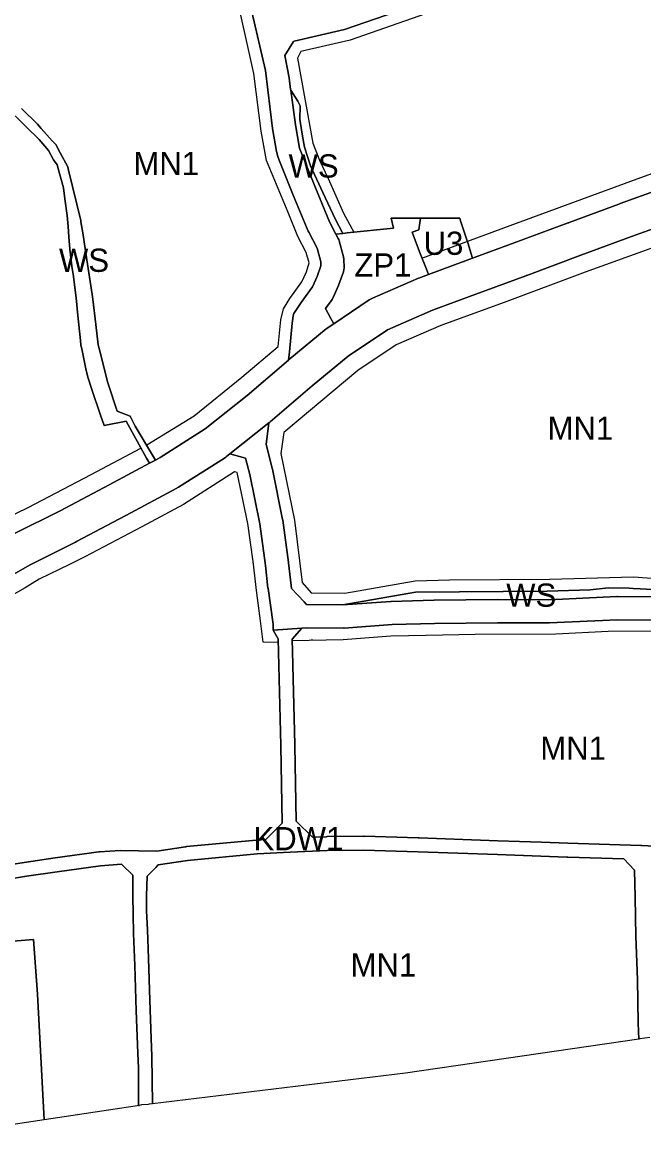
# Model space of a CAD drawing. Extents: x -284239 to -281592, y 34477 to 37267.
# Drawn here: x -283094 to -282826.9, y 34607.5 to 35089.5 of the extents above; entities that cross this region are included whole.
import ezdxf

# ---------------------------------------------------------------- set-up
doc = ezdxf.new("R2010")
doc.units = 0
for name, color, linetype in [('linie_rozgraniczajace', 7, 'Continuous'), ('linie_zabudowy_nieprzekraczalne', 7, 'Continuous'), ('oznaczenia_przeznaczen', 7, 'Continuous')]:
    doc.layers.add(name, color=color, linetype=linetype)

msp = doc.modelspace()

# ---------------------------------------------------------------- linework, layer by layer
at = {"layer": 'linie_rozgraniczajace'}
for points in [[(-282984.261, 35031.801), (-282984.727, 35033.927), (-282986.536, 35043.847), (-282986.543, 35043.898), (-282989.562, 35068.789), (-282995.429, 35094.107), (-282997.964, 35106.782), (-282997.992, 35107.066), (-282998.031, 35107.22), (-282999.546, 35121.106), (-283000.607, 35130.234), (-283002.988, 35136.929), (-283006.698, 35143.047), (-283012.879, 35144.669), (-283014.237, 35143.768), (-283014.294, 35143.738), (-283014.337, 35143.704), (-283037.155, 35129.353), (-283037.6, 35129.123), (-283037.687, 35129.062), (-283050.882, 35122.865), (-283072.146, 35113.651), (-283108.433, 35098.389)], [(-282888.924, 35109.624), (-282955.467, 35086.473), (-282977.23, 35081.468), (-282977.427, 35081.287), (-282981.158, 35075.35), (-282979.397, 35065.606), (-282978.732, 35060.692), (-282978.682, 35060.321), (-282976.677, 35045.517), (-282974.931, 35035.403), (-282974.367, 35034.009), (-282968.305, 35019.008), (-282961.945, 35003.744), (-282959.201, 34998.435), (-282958.219, 34996.535), (-282958.042, 34996.153), (-282957.836, 34995.549), (-282955.951, 34988.604), (-282955.825, 34987.656), (-282955.778, 34987.441), (-282955.679, 34984.068), (-282955.692, 34983.997), (-282955.677, 34983.92), (-282955.968, 34982.239), (-282957.953, 34976.682), (-282958.066, 34976.504), (-282958.113, 34976.289), (-282960.444, 34971.179), (-282960.537, 34971.045), (-282960.913, 34970.364), (-282963.722, 34966.398), (-282961.42, 34962.059), (-282960.194, 34959.875), (-282962.551, 34958.298), (-282963.138, 34957.816), (-282963.415, 34957.649), (-282978.997, 34944.716), (-282979.222, 34944.512), (-282979.282, 34944.474), (-282979.59, 34944.211), (-282979.251, 34947.75), (-282978.03, 34960.157), (-282977.949, 34961.052), (-282977.552, 34963.234), (-282977.253, 34964.253), (-282976.76, 34965.164), (-282974.18, 34968.934), (-282974.151, 34968.968), (-282974.133, 34969), (-282969.346, 34975.759), (-282967.299, 34980.246), (-282965.703, 34984.715), (-282965.757, 34986.555), (-282967.347, 34992.416), (-282970.923, 34999.336), (-282971.096, 34999.707), (-282977.567, 35015.236), (-282983.609, 35030.188), (-282984.261, 35031.801)], [(-282814.671, 35019.595), (-282837.032, 35011.566), (-282837.249, 35011.428), (-282837.567, 35011.371), (-282858.94, 35003.467), (-282859.141, 35003.338), (-282859.425, 35003.287), (-282882.548, 34994.655), (-282900.47, 34988.07), (-282901.252, 34990.443), (-282902.422, 34994.245), (-282905.721, 35004.142), (-282905.941, 35005.352), (-282922.86, 35005.352), (-282935.414, 35005.352), (-282934.534, 35000.953), (-282954.439, 34998.974), (-282955.226, 34998.885), (-282956.293, 34998.764), (-282959.504, 35005.043), (-282964.821, 35016.354), (-282970.138, 35027.76), (-282972.748, 35035.881), (-282973.811, 35041.391), (-282974.778, 35047.868), (-282974.584, 35053.668), (-282975.648, 35055.698), (-282978.682, 35060.321), (-282978.732, 35060.692), (-282979.397, 35065.606), (-282981.158, 35075.35), (-282977.427, 35081.287), (-282977.23, 35081.468), (-282955.467, 35086.473), (-282888.924, 35109.624)], [(-282995.429, 35094.107), (-282989.562, 35068.789), (-282986.543, 35043.898), (-282986.536, 35043.847), (-282984.727, 35033.927), (-282984.261, 35031.801), (-282983.609, 35030.188), (-282977.567, 35015.236), (-282971.096, 34999.707), (-282970.923, 34999.336), (-282967.347, 34992.416), (-282965.757, 34986.555), (-282965.703, 34984.715), (-282967.299, 34980.246), (-282969.346, 34975.759), (-282974.133, 34969), (-282974.151, 34968.968), (-282974.18, 34968.934), (-282976.76, 34965.164), (-282977.253, 34964.253), (-282977.552, 34963.234), (-282977.949, 34961.052), (-282978.03, 34960.157), (-282979.251, 34947.75), (-282979.59, 34944.211), (-282997.369, 34928.976), (-283015.4, 34914.591), (-283034.85, 34902.276), (-283036.848, 34901.207), (-283038.115, 34903.36), (-283045.51, 34915.78), (-283047.764, 34920.051), (-283053.281, 34922.246), (-283057.226, 34934.495), (-283059.242, 34942.266), (-283060.251, 34946.419), (-283061.408, 34950.779), (-283062.475, 34959.558), (-283063.692, 34970.503), (-283063.999, 34972.423), (-283066.274, 34987.41), (-283068.022, 34998.977), (-283068.852, 35003.722), (-283068.95, 35004.294), (-283074.187, 35025.877), (-283074.429, 35027.45), (-283077.75, 35033.442), (-283079.619, 35036.971), (-283081.161, 35038.632), (-283085.966, 35043.912), (-283087.568, 35045.691), (-283094.449, 35052.454)], [(-283101.538, 35053.67), (-283092.254, 35044.386), (-283086.886, 35039.136), (-283082.793, 35034.45), (-283080.598, 35030.416), (-283079.115, 35028.221), (-283078.551, 35026.116), (-283076.653, 35019.353), (-283076.356, 35018.285), (-283075.763, 35013.54), (-283074.725, 35006.392), (-283074.31, 35001.705), (-283074.073, 34997.256), (-283073.687, 34991.947), (-283072.738, 34984.591), (-283072.597, 34983.582), (-283072.256, 34981.13), (-283070.968, 34971.055), (-283070.128, 34963.414), (-283069.09, 34952.707), (-283068.852, 34950.749), (-283068.318, 34948.377), (-283066.568, 34939.686), (-283065.738, 34936.423), (-283064.314, 34932.034), (-283060.429, 34920.555), (-283058.916, 34916.017), (-283049.425, 34917.975), (-283040.607, 34902.026), (-283039.34, 34899.873), (-283056.665, 34890.604), (-283077.823, 34879.372), (-283097.47, 34869.563)], [(-283094.449, 35052.454), (-283087.568, 35045.691), (-283085.966, 35043.912), (-283081.161, 35038.632), (-283079.619, 35036.971), (-283077.75, 35033.442), (-283074.429, 35027.45), (-283074.187, 35025.877), (-283068.95, 35004.294), (-283068.852, 35003.722), (-283068.022, 34998.977), (-283066.274, 34987.41), (-283063.999, 34972.423), (-283063.692, 34970.503), (-283062.475, 34959.558), (-283061.408, 34950.779), (-283060.251, 34946.419), (-283059.242, 34942.266), (-283057.226, 34934.495), (-283053.281, 34922.246), (-283047.764, 34920.051), (-283045.51, 34915.78), (-283038.115, 34903.36), (-283036.848, 34901.207), (-283039.34, 34899.873), (-283040.607, 34902.026), (-283049.425, 34917.975), (-283058.916, 34916.017), (-283060.429, 34920.555), (-283064.314, 34932.034), (-283065.738, 34936.423), (-283066.568, 34939.686), (-283068.318, 34948.377), (-283068.852, 34950.749), (-283069.09, 34952.707), (-283070.128, 34963.414), (-283070.968, 34971.055), (-283072.256, 34981.13), (-283072.597, 34983.582), (-283072.738, 34984.591), (-283073.687, 34991.947), (-283074.073, 34997.256), (-283074.31, 35001.705), (-283074.725, 35006.392), (-283075.763, 35013.54), (-283076.356, 35018.285), (-283076.653, 35019.353), (-283078.551, 35026.116), (-283079.115, 35028.221), (-283080.598, 35030.416), (-283082.793, 35034.45), (-283086.886, 35039.136), (-283092.254, 35044.386), (-283101.538, 35053.67)], [(-282903.935, 34986.797), (-282900.47, 34988.07), (-282882.548, 34994.655), (-282859.425, 35003.287), (-282859.141, 35003.338), (-282858.94, 35003.467), (-282837.567, 35011.371), (-282837.249, 35011.428), (-282837.032, 35011.566), (-282814.671, 35019.595)], [(-282809.83, 35005.391), (-282832.188, 34997.363), (-282853.979, 34989.304), (-282877.109, 34980.67), (-282877.403, 34980.617), (-282877.61, 34980.485), (-282899.009, 34972.622), (-282917.668, 34965.729), (-282937.057, 34957.308), (-282953.985, 34945.976), (-282969.414, 34933.171), (-282987.556, 34917.625), (-282987.643, 34917.572), (-282987.964, 34917.285), (-282988.027, 34917.234), (-283004.812, 34903.844), (-283006.225, 34902.716), (-283006.598, 34902.497), (-283007.144, 34902.059), (-283026.964, 34889.51), (-283027.497, 34889.233), (-283027.692, 34889.089)], [(-282803.33, 34844.5), (-282828.459, 34845.767), (-282831.371, 34845.965), (-282831.573, 34845.958), (-282833.09, 34846.07), (-282842.04, 34846.18), (-282849.95, 34845.359), (-282868.422, 34844.757), (-282925.004, 34844.354), (-282956.239, 34838.916), (-282971.909, 34839.04), (-282972.937, 34840.153), (-282978.282, 34845.943), (-282978.331, 34845.983), (-282978.506, 34847.232), (-282979.567, 34856.984), (-282979.573, 34857.086), (-282982.087, 34875.343), (-282982.121, 34875.469), (-282982.14, 34875.653), (-282986.505, 34897.216), (-282986.614, 34897.573), (-282986.639, 34897.732), (-282989.227, 34907.941), (-282988.027, 34917.234), (-282987.964, 34917.285), (-282987.643, 34917.572), (-282987.556, 34917.625), (-282969.414, 34933.171), (-282953.985, 34945.976), (-282937.057, 34957.308), (-282917.668, 34965.729), (-282899.009, 34972.622), (-282877.61, 34980.485), (-282877.403, 34980.617), (-282877.109, 34980.67), (-282853.979, 34989.304), (-282832.188, 34997.363), (-282809.83, 35005.391)], [(-283097.47, 34869.563), (-283077.823, 34879.372), (-283056.665, 34890.604), (-283039.34, 34899.873), (-283036.848, 34901.207), (-283034.85, 34902.276), (-283015.4, 34914.591), (-282997.369, 34928.976), (-282979.59, 34944.211), (-282979.282, 34944.474), (-282979.222, 34944.512), (-282978.997, 34944.716), (-282963.415, 34957.649), (-282963.138, 34957.816), (-282962.551, 34958.298), (-282960.194, 34959.875), (-282944.943, 34970.085), (-282943.475, 34970.87), (-282943.44, 34970.894), (-282923.689, 34979.473), (-282923.203, 34979.574), (-282922.81, 34979.825), (-282919.422, 34981.077), (-282904.41, 34986.622), (-282904.131, 34986.672), (-282903.935, 34986.797)], [(-283004.812, 34903.844), (-282988.027, 34917.234), (-282989.227, 34907.941), (-282986.639, 34897.732), (-282986.614, 34897.573), (-282986.505, 34897.216), (-282982.14, 34875.653), (-282982.121, 34875.469), (-282982.087, 34875.343), (-282979.573, 34857.086), (-282979.567, 34856.984), (-282978.506, 34847.232), (-282978.331, 34845.983), (-282978.282, 34845.943), (-282972.937, 34840.153), (-282971.909, 34839.04), (-282956.239, 34838.916), (-282935.664, 34840.358), (-282935.574, 34840.343), (-282935.458, 34840.368), (-282917.069, 34840.897), (-282917.03, 34840.89), (-282916.986, 34840.899), (-282889.8, 34841.23), (-282889.755, 34841.221), (-282889.71, 34841.23), (-282867.75, 34841.099), (-282838.448, 34842.481), (-282838.318, 34842.459), (-282838.174, 34842.487), (-282823.206, 34842.374)], [(-283109.417, 34845.453), (-283090.756, 34856.145), (-283071.218, 34865.899), (-283071.156, 34865.944), (-283070.818, 34866.103), (-283049.783, 34877.27), (-283049.73, 34877.309), (-283049.543, 34877.398), (-283027.692, 34889.089), (-283027.497, 34889.233), (-283026.964, 34889.51), (-283007.144, 34902.059), (-283006.598, 34902.497), (-283006.225, 34902.716), (-283004.812, 34903.844), (-282998.149, 34902.078), (-282996.254, 34894.971), (-282991.972, 34873.823), (-282989.49, 34855.795), (-282988.44, 34846.078), (-282988.428, 34846.031), (-282988.42, 34845.92), (-282986.275, 34830.649), (-282986.198, 34827.995), (-282984.083, 34824.23), (-282983.755, 34812.865), (-282982.896, 34778.419), (-282982.278, 34744.959), (-282989.315, 34737.922), (-282993.258, 34737.701), (-282993.296, 34737.692), (-282993.587, 34737.678), (-283023.488, 34734.852), (-283023.583, 34734.829), (-283023.878, 34734.807), (-283036.299, 34732.917), (-283052.013, 34733.25), (-283060.941, 34732.578), (-283060.979, 34732.569), (-283061.115, 34732.56), (-283079.954, 34730.032), (-283079.993, 34730.027), (-283093.246, 34728.035), (-283110.839, 34725.25)], [(-282821.234, 34832.359), (-282838.113, 34832.486), (-282867.411, 34831.103), (-282867.537, 34831.125), (-282867.677, 34831.098), (-282877.381, 34831.156), (-282883.785, 34831.194), (-282889.724, 34831.23), (-282916.823, 34830.9), (-282935.067, 34830.375), (-282955.734, 34828.927), (-282955.913, 34828.956), (-282956.123, 34828.915), (-282971.722, 34829.038), (-282973.902, 34828.881), (-282986.198, 34827.995), (-282986.275, 34830.649), (-282988.42, 34845.92), (-282988.428, 34846.031), (-282988.44, 34846.078), (-282989.49, 34855.795), (-282991.972, 34873.823), (-282996.254, 34894.971), (-282998.149, 34902.078), (-283004.812, 34903.844)], [(-283027.692, 34889.089), (-283049.543, 34877.398), (-283049.73, 34877.309), (-283049.783, 34877.27), (-283070.818, 34866.103), (-283071.156, 34865.944), (-283071.218, 34865.899), (-283090.756, 34856.145), (-283109.417, 34845.453)], [(-282823.206, 34842.374), (-282838.174, 34842.487), (-282838.318, 34842.459), (-282838.448, 34842.481), (-282867.75, 34841.099), (-282889.71, 34841.23), (-282889.755, 34841.221), (-282889.8, 34841.23), (-282916.986, 34840.899), (-282917.03, 34840.89), (-282917.069, 34840.897), (-282935.458, 34840.368), (-282935.574, 34840.343), (-282935.664, 34840.358), (-282956.239, 34838.916), (-282925.004, 34844.354), (-282868.422, 34844.757), (-282849.95, 34845.359), (-282842.04, 34846.18), (-282833.09, 34846.07), (-282831.573, 34845.958), (-282831.371, 34845.965), (-282828.459, 34845.767), (-282803.33, 34844.5)], [(-282803.55, 34733.997), (-282827.697, 34735.363), (-282827.913, 34735.327), (-282828.185, 34735.385), (-282859.477, 34736.305), (-282870.907, 34736.732), (-282880.271, 34737.082), (-282889.562, 34737.429), (-282923.413, 34738.678), (-282923.608, 34738.643), (-282923.837, 34738.692), (-282946.991, 34739.343), (-282947.254, 34739.294), (-282947.528, 34739.347), (-282962.943, 34739.153), (-282963.208, 34739.099), (-282963.437, 34739.14), (-282969.348, 34738.895), (-282976.331, 34745.752), (-282976.894, 34778.354), (-282976.939, 34778.572), (-282976.903, 34778.769), (-282977.753, 34812.837), (-282977.799, 34813.055), (-282977.764, 34813.246), (-282978.051, 34824.157), (-282973.902, 34828.881), (-282971.722, 34829.038), (-282956.123, 34828.915), (-282955.913, 34828.956), (-282955.734, 34828.927), (-282935.067, 34830.375), (-282916.823, 34830.9), (-282889.724, 34831.23), (-282883.785, 34831.194), (-282877.381, 34831.156), (-282867.677, 34831.098), (-282867.537, 34831.125), (-282867.411, 34831.103), (-282838.113, 34832.486), (-282821.234, 34832.359)], [(-283110.839, 34725.25), (-283093.246, 34728.035), (-283079.993, 34730.027), (-283079.954, 34730.032), (-283061.115, 34732.56), (-283060.979, 34732.569), (-283060.941, 34732.578), (-283052.013, 34733.25), (-283036.299, 34732.917), (-283023.878, 34734.807), (-283023.583, 34734.829), (-283023.488, 34734.852), (-282993.587, 34737.678), (-282993.296, 34737.692), (-282993.258, 34737.701), (-282989.315, 34737.922), (-282982.278, 34744.959), (-282982.896, 34778.419), (-282983.755, 34812.865), (-282984.083, 34824.23), (-282986.198, 34827.995), (-282973.902, 34828.881), (-282978.051, 34824.157), (-282977.764, 34813.246), (-282977.799, 34813.055), (-282977.753, 34812.837), (-282976.903, 34778.769), (-282976.939, 34778.572), (-282976.894, 34778.354), (-282976.331, 34745.752), (-282969.348, 34738.895), (-282963.437, 34739.14), (-282963.208, 34739.099), (-282962.943, 34739.153), (-282947.528, 34739.347), (-282947.254, 34739.294), (-282946.991, 34739.343), (-282923.837, 34738.692), (-282923.608, 34738.643), (-282923.413, 34738.678), (-282889.562, 34737.429), (-282880.271, 34737.082), (-282870.907, 34736.732), (-282859.477, 34736.305), (-282828.185, 34735.385), (-282827.913, 34735.327), (-282827.697, 34735.363), (-282803.55, 34733.997)], [(-282830.825, 34724.799), (-282835.505, 34729.598), (-282859.483, 34730.303), (-282859.711, 34730.352), (-282859.905, 34730.317), (-282889.785, 34731.433), (-282923.836, 34732.69), (-282947.31, 34733.349), (-282963.015, 34733.152), (-282978.957, 34732.493), (-282993.033, 34731.704), (-283022.993, 34728.872), (-283035.708, 34726.985), (-283036.647, 34725.87), (-283040.406, 34722.225), (-283040.61, 34713.685), (-283040.61, 34707.172), (-283040.263, 34699.096), (-283039.829, 34686.678), (-283039.265, 34668.833), (-283038.613, 34652.29), (-283038.353, 34644.648), (-283038.159, 34624.178), (-283039.55, 34624.01), (-283039.982, 34623.969), (-283042.82, 34623.7), (-283043.809, 34623.53), (-283044.041, 34623.503), (-283044.171, 34639.525), (-283044.345, 34645.951), (-283045.083, 34664.231), (-283045.734, 34683.726), (-283046.266, 34697.437), (-283046.472, 34705.826), (-283046.602, 34713.685), (-283046.532, 34722.569), (-283051.367, 34727.282), (-283060.404, 34726.602), (-283079.125, 34724.09), (-283092.332, 34722.105), (-283109.965, 34719.313)], [(-283079.125, 34724.09), (-283060.404, 34726.602), (-283051.367, 34727.282), (-283046.532, 34722.569), (-283046.602, 34713.685), (-283046.472, 34705.826), (-283046.266, 34697.437), (-283045.734, 34683.726), (-283045.083, 34664.231), (-283044.345, 34645.951), (-283044.171, 34639.525), (-283044.041, 34623.503), (-283043.809, 34623.53), (-283045.55, 34623.23), (-283084.608, 34617.309), (-283084.61, 34617.336), (-283087.577, 34671.417), (-283089.286, 34694.95), (-283089.366, 34694.946), (-283113.779, 34692.913)], [(-282824.22, 34652.68), (-282828.53, 34652.1), (-282828.996, 34652.032), (-282829.337, 34658.907), (-282829.491, 34677.744), (-282830.322, 34696.165), (-282830.315, 34696.205), (-282830.324, 34696.251), (-282830.602, 34713.172), (-282830.825, 34724.799)], [(-283109.965, 34719.313), (-283092.332, 34722.105), (-283079.125, 34724.09)], [(-283113.779, 34692.913), (-283089.366, 34694.946), (-283089.286, 34694.95), (-283087.577, 34671.417), (-283084.61, 34617.336), (-283084.608, 34617.309), (-283149.24, 34607.51)]]:
    msp.add_lwpolyline(points, dxfattribs=at)
for points in [[(-282978.682, 35060.321), (-282975.648, 35055.698), (-282974.584, 35053.668), (-282974.778, 35047.868), (-282973.811, 35041.391), (-282972.748, 35035.881), (-282970.138, 35027.76), (-282964.821, 35016.354), (-282959.504, 35005.043), (-282956.293, 34998.764), (-282959.201, 34998.435), (-282961.945, 35003.744), (-282968.305, 35019.008), (-282974.367, 35034.009), (-282974.931, 35035.403), (-282976.677, 35045.517)], [(-282963.722, 34966.398), (-282960.913, 34970.364), (-282960.537, 34971.045), (-282960.444, 34971.179), (-282958.113, 34976.289), (-282958.066, 34976.504), (-282957.953, 34976.682), (-282955.968, 34982.239), (-282955.677, 34983.92), (-282955.692, 34983.997), (-282955.679, 34984.068), (-282955.778, 34987.441), (-282955.825, 34987.656), (-282955.951, 34988.604), (-282957.836, 34995.549), (-282958.042, 34996.153), (-282958.219, 34996.535), (-282959.201, 34998.435), (-282956.293, 34998.764), (-282955.226, 34998.885), (-282954.439, 34998.974), (-282934.534, 35000.953), (-282935.414, 35005.352), (-282922.86, 35005.352), (-282923.647, 35000.238), (-282926.506, 34999.248), (-282923.317, 34990.781), (-282920.295, 34983.416), (-282919.422, 34981.077), (-282922.81, 34979.825), (-282923.203, 34979.574), (-282923.689, 34979.473), (-282943.44, 34970.894), (-282943.475, 34970.87), (-282944.943, 34970.085), (-282960.194, 34959.875), (-282961.42, 34962.059)], [(-282926.506, 34999.248), (-282923.647, 35000.238), (-282922.86, 35005.352), (-282905.941, 35005.352), (-282905.721, 35004.142), (-282902.422, 34994.245), (-282901.252, 34990.443), (-282900.47, 34988.07), (-282903.935, 34986.797), (-282904.131, 34986.672), (-282904.41, 34986.622), (-282919.422, 34981.077), (-282920.295, 34983.416), (-282923.317, 34990.781)], [(-283040.61, 34707.172), (-283040.61, 34713.685), (-283040.406, 34722.225), (-283036.647, 34725.87), (-283035.708, 34726.985), (-283022.993, 34728.872), (-282993.033, 34731.704), (-282978.957, 34732.493), (-282963.015, 34733.152), (-282947.31, 34733.349), (-282923.836, 34732.69), (-282889.785, 34731.433), (-282859.905, 34730.317), (-282859.711, 34730.352), (-282859.483, 34730.303), (-282835.505, 34729.598), (-282830.825, 34724.799), (-282830.602, 34713.172), (-282830.324, 34696.251), (-282830.315, 34696.205), (-282830.322, 34696.165), (-282829.491, 34677.744), (-282829.337, 34658.907), (-282828.996, 34652.032), (-282929.38, 34637.33), (-283038.159, 34624.178), (-283038.353, 34644.648), (-283038.613, 34652.29), (-283039.265, 34668.833), (-283039.829, 34686.678), (-283040.263, 34699.096)]]:
    msp.add_lwpolyline(points, close=True, dxfattribs=at)
at = {"layer": 'linie_zabudowy_nieprzekraczalne'}
for points in [[(-283040.526, 34907.716), (-283020.153, 34920.284), (-282999.648, 34936.887), (-282984.038, 34950.116), (-282982.847, 34961.493), (-282981.789, 34966.322), (-282979.01, 34970.687), (-282973.851, 34977.963), (-282971.867, 34982.197), (-282970.676, 34986.033), (-282971.999, 34990.531), (-282975.571, 34997.41), (-282979.804, 35007.663), (-282989.065, 35030.153), (-282991.314, 35042.72), (-282994.489, 35067.525), (-283002.955, 35105.691), (-283005.469, 35128.578), (-283007.321, 35134.266), (-283010.099, 35138.764), (-283011.951, 35139.293), (-283035.367, 35124.609), (-283059.444, 35113.695), (-283106.408, 35093.719)], [(-282905.985, 35098.415), (-282953.081, 35081.879), (-282974.248, 35077.05), (-282975.703, 35074.14), (-282969.088, 35037.593), (-282966.31, 35030.317), (-282962.606, 35022.38), (-282955.992, 35007.431), (-282951.494, 34999.229)], [(-282922.257, 34988.15), (-282884.289, 35002.107), (-282832.431, 35021.157), (-282796.977, 35034.121)], [(-282760.2, 35012.425), (-282761.258, 35012.425), (-282770.121, 35010.573), (-282787.319, 35005.679), (-282824.229, 34992.119), (-282852.01, 34982.064), (-282886.935, 34969.034), (-282914.055, 34959.112), (-282933.37, 34950.777), (-282949.774, 34939.731), (-282981.656, 34913.008), (-282982.847, 34904.012), (-282977.026, 34875.371), (-282973.719, 34848.516), (-282969.882, 34844.018), (-282955.462, 34843.886), (-282925.172, 34849.266), (-282910.356, 34849.663), (-282867.229, 34849.927), (-282831.245, 34850.986), (-282803.861, 34849.001), (-282798.043, 34849.821), (-282750.679, 34859.055), (-282743.36, 34860.31)], [(-283101.645, 34875.966), (-283091.591, 34880.861), (-283064.471, 34895.016), (-283043.172, 34906.261)], [(-282984.307, 34822.675), (-282990.525, 34822.807), (-282991.626, 34832.08), (-282993.298, 34843.952), (-282994.753, 34857.578), (-282997.134, 34873.85), (-283001.632, 34895.81), (-283002.823, 34896.075), (-283024.783, 34882.118), (-283042.643, 34872.461), (-283067.249, 34859.628), (-283073.731, 34856.255), (-283086.828, 34849.905), (-283092.781, 34846.201), (-283105.217, 34839.321)], [(-282701.869, 34706.478), (-282718.924, 34732.893), (-282725.936, 34740.962), (-282731.36, 34746.849), (-282750.542, 34766.693), (-282773.429, 34789.249), (-282782.292, 34797.716), (-282795.125, 34809.093), (-282807.56, 34821.396), (-282813.116, 34825.365), (-282822.244, 34827.548), (-282842.221, 34827.415), (-282864.71, 34826.291), (-282899.371, 34826.158), (-282920.405, 34825.762), (-282935.619, 34825.365), (-282956.124, 34823.909), (-282978.089, 34823.469)], [(-282969.485, 34824.174), (-282969.602, 34824.029)]]:
    msp.add_lwpolyline(points, dxfattribs=at)

# ---------------------------------------------------------------- texts
at = {"layer": 'oznaczenia_przeznaczen'}
for s, p in [('MN1', (-283046.296, 35023.817)), ('WS', (-282979.592, 35022.76)), ('U3', (-282921.532, 34989.505)), ('WS', (-283078.309, 34982.181)), ('ZP1', (-282951.302, 34980.152)), ('MN1', (-282868.254, 34909.928)), ('WS', (-282886.02, 34838.088)), ('MN1', (-282871.341, 34772.213)), ('KDW1', (-282994.663, 34733.306)), ('MN1', (-282952.919, 34678.969))]:
    msp.add_text(s, height=10, dxfattribs=at).set_placement(p)

doc.saveas('drawing.dxf')
